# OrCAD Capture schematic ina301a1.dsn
size A; title: INA293 40-V High-Voltage, High Bandwidth, Unidirectional, 110-V Common-Mode Current-Sense Amplifier; rev: A; note: SBOS870
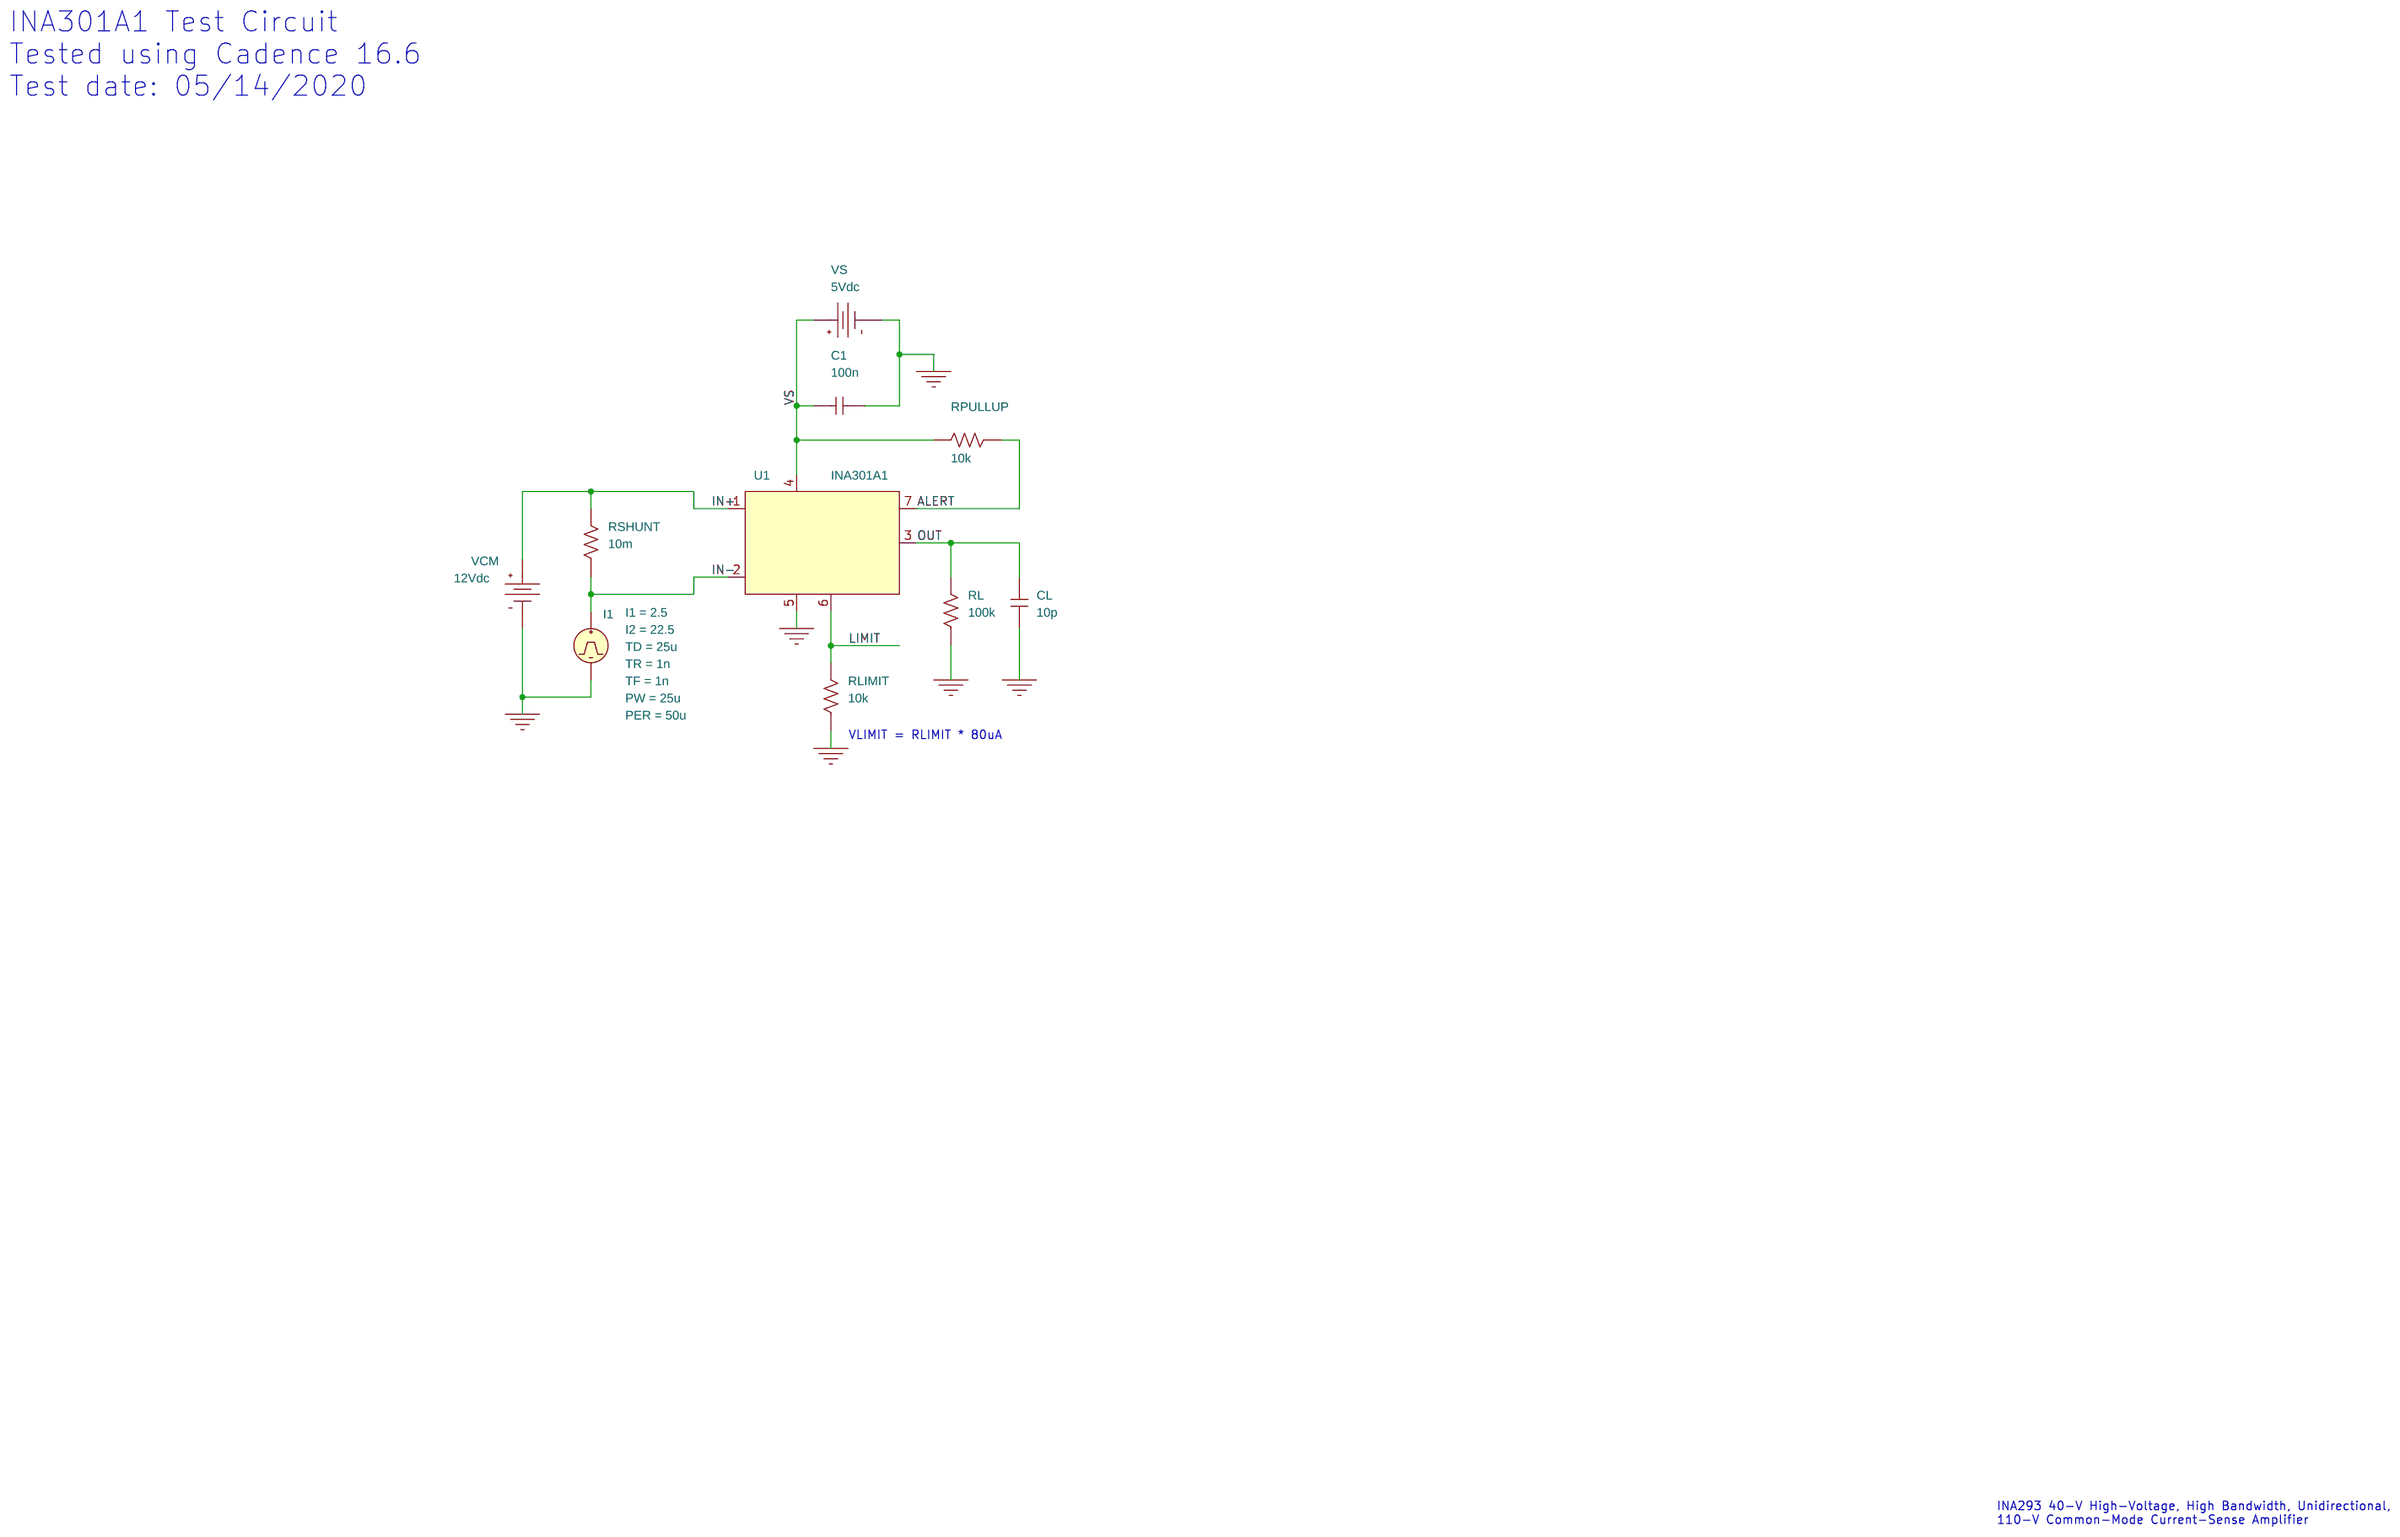
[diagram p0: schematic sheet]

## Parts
C1  100n  [RAD/CK05]
CL  10p  [RAD/CK05]
I1  IPULSE
RL  100k  [AX/RC05]
RLIMIT  10k  [AX/RC05]
RPULLUP  10k  [AX/RC05]
RSHUNT  10m  [AX/RC05]
U1  INA301A1
VCM  VDC
VS  VDC

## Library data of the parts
C1 CL = C
I1 = IPULSE: I1: 2.5; I2: 22.5; PER: 50u; PW: 25u; TD: 25u; TF: 1n; TR: 1n
RL RLIMIT RPULLUP RSHUNT = R
U1 = INA301A1
VCM = VDC: DC: 12Vdc
VS = VDC: DC: 5Vdc

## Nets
0: C1.1 CL.1 I1.2(-) RL.1 RLIMIT.1 U1.5(GND) VCM.1(-) VS.1(-)
ALERT: RPULLUP.1 U1.7(ALERT)
IN+: RSHUNT.2 U1.1(INP) VCM.0(+)
IN-: I1.1(+) RSHUNT.1 U1.2(INN)
LIMIT: RLIMIT.2 U1.6(LIMIT)
OUT: CL.2 RL.2 U1.3(OUT)
VS: C1.2 RPULLUP.2 U1.4(VS) VS.0(+)

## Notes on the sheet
- INA301A1 Test Circuit
  Tested using Cadence 16.6
  Test date: 05/14/2020
- VLIMIT = RLIMIT * 80uA
- INA293 40-V High-Voltage, High Bandwidth, Unidirectional,
  110-V Common-Mode Current-Sense Amplifier
